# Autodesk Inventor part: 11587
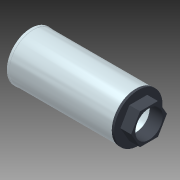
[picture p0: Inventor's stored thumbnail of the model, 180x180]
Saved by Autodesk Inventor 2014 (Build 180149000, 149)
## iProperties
Shininess: 20.0
Length Units: 11272
Angle Units: 11279
Time Units: 11290
Mass Units: 11286
Length Display Precision: 3
Angle Display Precision: 2
Company: Autodesk, Inc.
Created: 2002-06
Part Number: 11587
Material: Stainless Steel 316
Description: FILTER, STRAINER
Document SubType Name: Modeling
Designer: Autodesk, Inc.
Density: 8.182 g/cm^3
Mass: 8948.16 g
Surface Area: 2792.32 cm^2
Volume: 1093.64 cm^3
Appearance: Stainless Steel
Density: 0.0
Volumn: 0.0
Area: 0.0
PropertySet Name: Model Information
Control State: 0
Master: False
Checked Out: False
Last Check In By: JT
Last Check In Date: 2003-06-20
Title: FILTER, STRAINER
Author: Autodesk, Inc.
Comments: PORT IS 2 1/2" NPT
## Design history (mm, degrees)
sketch "Sketch1"
  geometry: L1 (0, 63.5)-(-273.05, 63.5); L2 (-273.05, 63.5)-(-273.05, 64.294); L3 (-273.05, 64.294)-(-279.4, 64.294); L4 (-279.4, 64.294)-(-279.4, 51.594); L5 (-279.4, 51.594)-(-277.019, 51.594); L6 (-277.019, 51.594)-(-277.019, 25.4); L7 (-277.019, 25.4)-(-279.4, 25.4); L8 (-279.4, 25.4)-(-279.4, 0); L9 (0, 0)-(-208.327, 0); L10 (0, 63.5)-(0, 57.15); L11 (0, 57.15)-(-269.875, 57.15); L12 (-269.875, 57.15)-(-269.875, 38.1); L13 (-269.875, 38.1)-(-219.075, 38.1); L14 (-219.075, 38.1)-(-219.075, 0); L15 (-219.075, 0)-(-279.4, 0)
  constraints: 30 end point, 6 parallel, 5 perpendicular, 1 collinear, 1 horizontal, 1 horizontal alignment, 1 point on line, 1 vertical alignment
  dimensions: "d3" = 127 diameter of L1 L9; "d4" = 128.5875 diameter of L3 L9; "d5" = 6.35 distance between parallel lines of L1 L11; "d6" = 6.35 distance of L2.end L3.end; "d7" = 279.4 distance between parallel lines of L4 L10; "d8" = 50.8 diameter of L7 L9; "d9" = 2.38125 distance between parallel lines of L8 L6; "d10" = 12.7 distance of L3.end L4.end; "d11" = 9.525 distance between parallel lines of L4 L12; "d12" = 76.2 diameter of L13 L9; "d13" = 50.8 distance between parallel lines of L12 L14
revolve "Revolution1" sketch "Sketch1" stored, may be unused: angle "d14" = 90 deg
sketch "Sketch2"
  geometry: C1 r 64.294 at (0, 0) reference; C2 r 36.513 at (0, 0)
  constraints: 1 centre point, 1 coincident
  dimensions: "d15" = 73.025 diameter of C2
extrude "Extrusion2" join sketch "Sketch2" distance "d16" = 6.35; taper "d17" = 0 deg
sketch "Sketch3"
  geometry: L1 (-23.83, -41.275)-(-47.66, 0); L2 (-47.66, 0)-(-23.83, 41.275); L3 (-23.83, 41.275)-(23.83, 41.275); L4 (23.83, 41.275)-(47.66, 0); L5 (47.66, 0)-(23.83, -41.275); L6 (23.83, -41.275)-(-23.83, -41.275); C1 r 36.512 at (0, 0) reference; C2 r 64.294 at (0, 0) reference; 1 further point
  constraints: 12 end point, 1 coincident, 1 horizontal, 11 other
  dimensions: "d18" = 82.55 distance between parallel lines of L6 L3
extrude "Extrusion3" join sketch "Sketch3" distance "d19" = 28.575; taper "d20" = 0 deg
body "Solid1"
